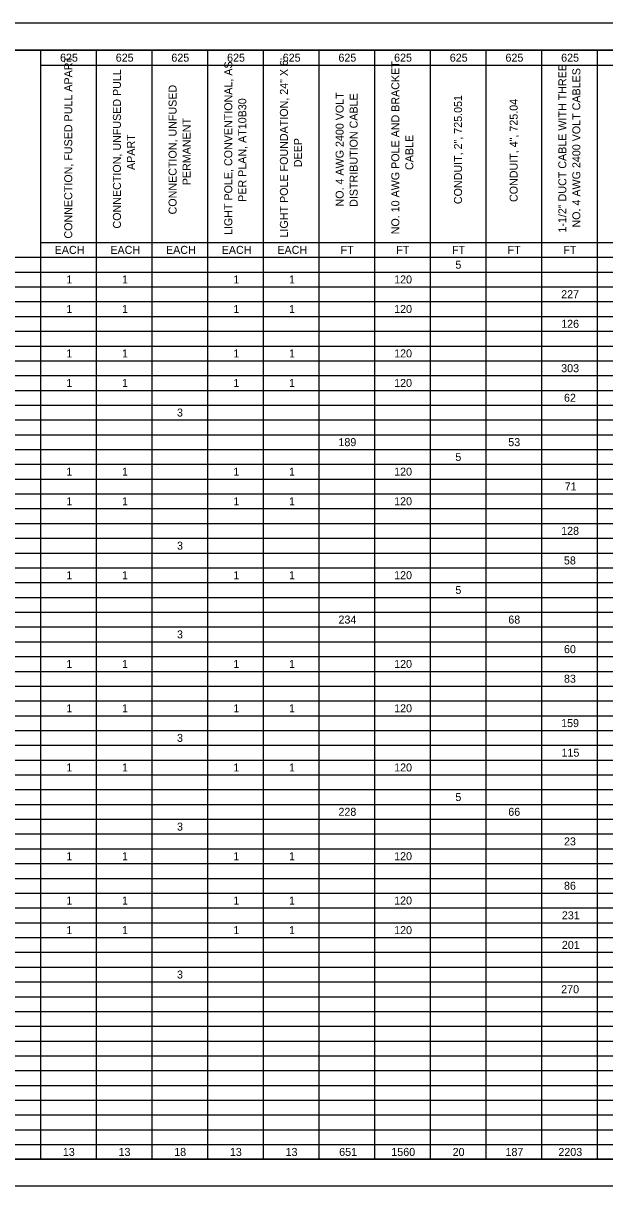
# Model space of a CAD drawing. Extents: x 0 to 34, y 0 to 22.
# Drawn here: x 11.66 to 22.66, y 0 to 22 of the extents above; entities that cross this region are included whole.
import ezdxf

# ---------------------------------------------------------------- set-up
doc = ezdxf.new("R2010")
doc.units = 0
for name, color, linetype in [('Default', 7, 'Continuous'), ('SH_Border', 7, 'Continuous'), ('SH_Cut_Line', 7, 'Continuous')]:
    doc.layers.add(name, color=color, linetype=linetype)

msp = doc.modelspace()

# ---------------------------------------------------------------- linework, layer by layer
at = {"layer": 'Default'}
for p, q in [((1.496, 21.489), (32, 21.489)), ((11.982, 21.489), (11.982, 0.78)), ((13.036, 21.489), (13.036, 0.5)), ((14.089, 21.489), (14.089, 0.5)), ((15.143, 21.489), (15.143, 0.5)), ((16.196, 21.489), (16.196, 0.5)), ((17.25, 21.489), (17.25, 0.5)), ((18.304, 21.489), (18.304, 0.5)), ((19.357, 21.489), (19.357, 0.5)), ((20.411, 21.489), (20.411, 0.5)), ((21.464, 21.489), (21.464, 0.5)), ((22.518, 21.489), (22.518, 0.5)), ((11.982, 21.209), (32, 21.209)), ((11.982, 17.851), (32, 17.851)), ((1.496, 17.571), (32, 17.571)), ((1.496, 17.291), (32, 17.291)), ((1.496, 17.011), (32, 17.011)), ((1.496, 16.732), (32, 16.732)), ((1.496, 16.452), (32, 16.452)), ((1.496, 16.172), (32, 16.172)), ((1.496, 15.892), (32, 15.892)), ((1.496, 15.612), (32, 15.612)), ((1.496, 15.332), (32, 15.332)), ((1.496, 15.052), (32, 15.052)), ((1.496, 14.773), (32, 14.773)), ((1.496, 14.493), (32, 14.493)), ((1.496, 14.213), (32, 14.213)), ((1.496, 13.933), (32, 13.933)), ((1.496, 13.653), (32, 13.653)), ((1.496, 13.373), (32, 13.373)), ((1.496, 13.093), (32, 13.093)), ((1.496, 12.814), (32, 12.814)), ((1.496, 12.534), (32, 12.534)), ((1.496, 12.254), (32, 12.254)), ((1.496, 11.974), (32, 11.974)), ((1.496, 11.694), (32, 11.694)), ((1.496, 11.414), (32, 11.414)), ((1.496, 11.134), (32, 11.134)), ((1.496, 10.855), (32, 10.855)), ((1.496, 10.575), (32, 10.575)), ((1.496, 10.295), (32, 10.295)), ((1.496, 10.015), (32, 10.015)), ((1.496, 9.735), (32, 9.735)), ((1.496, 9.455), (32, 9.455)), ((1.496, 9.175), (32, 9.175)), ((1.496, 8.896), (32, 8.896)), ((1.496, 8.616), (32, 8.616)), ((1.496, 8.336), (32, 8.336)), ((1.496, 8.056), (32, 8.056)), ((1.496, 7.776), (32, 7.776)), ((1.496, 7.496), (32, 7.496)), ((1.496, 7.217), (32, 7.217)), ((1.496, 6.937), (32, 6.937)), ((1.496, 6.657), (32, 6.657)), ((1.496, 6.377), (32, 6.377)), ((1.496, 6.097), (32, 6.097)), ((1.496, 5.817), (32, 5.817)), ((1.496, 5.537), (32, 5.537)), ((1.496, 5.258), (32, 5.258)), ((1.496, 4.978), (32, 4.978)), ((1.496, 4.698), (32, 4.698)), ((1.496, 4.418), (32, 4.418)), ((1.496, 4.138), (32, 4.138)), ((1.496, 3.858), (32, 3.858)), ((1.496, 3.578), (32, 3.578)), ((1.496, 3.299), (32, 3.299)), ((1.496, 3.019), (32, 3.019)), ((1.496, 2.739), (32, 2.739)), ((1.496, 2.459), (32, 2.459)), ((1.496, 2.179), (32, 2.179)), ((1.496, 1.899), (32, 1.899)), ((1.496, 1.619), (32, 1.619)), ((1.496, 1.34), (32, 1.34)), ((1.496, 1.06), (32, 1.06)), ((1.496, 0.78), (32, 0.78)), ((11.982, 0.78), (11.982, 0.5)), ((1.496, 0.5), (32, 0.5))]:
    msp.add_line(p, q, dxfattribs=at)
at = {"layer": 'SH_Border'}
msp.add_lwpolyline([(1.5, 21.5), (33.5, 21.5), (33.5, 0.5), (1.5, 0.5)], close=True, dxfattribs=at)
at = {"layer": 'SH_Cut_Line'}
msp.add_lwpolyline([(0, 0), (34, 0), (34, 22), (0, 22)], close=True, dxfattribs=at)

# ---------------------------------------------------------------- texts
at = {"layer": 'Default'}
for s, height, p in [('625', 0.1515, (12.354, 21.273)), ('625', 0.1515, (13.408, 21.273)), ('625', 0.1515, (14.461, 21.273)), ('625', 0.1515, (15.515, 21.273)), ('625', 0.1515, (16.568, 21.273)), ('625', 0.1515, (17.622, 21.273)), ('625', 0.1515, (18.675, 21.273)), ('625', 0.1515, (19.729, 21.273)), ('625', 0.1515, (20.783, 21.273)), ('625', 0.1515, (21.836, 21.273)), ('EACH', 0.1515, (12.252, 17.635)), ('EACH', 0.1515, (13.306, 17.635)), ('EACH', 0.1515, (14.359, 17.635)), ('EACH', 0.1515, (15.413, 17.635)), ('EACH', 0.1515, (16.466, 17.635)), ('FT', 0.1515, (17.662, 17.635)), ('FT', 0.1515, (18.716, 17.635)), ('FT', 0.1515, (19.77, 17.635)), ('FT', 0.1515, (20.823, 17.635)), ('FT', 0.1515, (21.877, 17.635)), ('5', 0.151, (19.835, 17.355)), ('1', 0.151, (12.474, 17.076)), ('1', 0.151, (13.527, 17.076)), ('1', 0.151, (15.634, 17.076)), ('1', 0.151, (16.688, 17.076)), ('120', 0.1515, (18.676, 17.076)), ('227', 0.1515, (21.837, 16.796)), ('1', 0.151, (12.474, 16.516)), ('1', 0.151, (13.527, 16.516)), ('1', 0.151, (15.634, 16.516)), ('1', 0.151, (16.688, 16.516)), ('120', 0.1515, (18.676, 16.516)), ('126', 0.1515, (21.837, 16.236)), ('1', 0.151, (12.474, 15.676)), ('1', 0.151, (13.527, 15.676)), ('1', 0.151, (15.634, 15.676)), ('1', 0.151, (16.688, 15.676)), ('120', 0.1515, (18.676, 15.676)), ('303', 0.1515, (21.837, 15.396)), ('1', 0.151, (12.474, 15.117)), ('1', 0.151, (13.527, 15.117)), ('1', 0.151, (15.634, 15.117)), ('1', 0.151, (16.688, 15.117)), ('120', 0.1515, (18.676, 15.117)), ('62', 0.1515, (21.89, 14.837)), ('3', 0.151, (14.567, 14.557)), ('189', 0.1515, (17.622, 13.997)), ('53', 0.1515, (20.836, 13.997)), ('5', 0.151, (19.835, 13.717)), ('1', 0.151, (12.474, 13.438)), ('1', 0.151, (13.527, 13.438)), ('1', 0.151, (15.634, 13.438)), ('1', 0.151, (16.688, 13.438)), ('120', 0.1515, (18.676, 13.438)), ('71', 0.1515, (21.903, 13.158)), ('1', 0.151, (12.474, 12.878)), ('1', 0.151, (13.527, 12.878)), ('1', 0.151, (15.634, 12.878)), ('1', 0.151, (16.688, 12.878)), ('120', 0.1515, (18.676, 12.878)), ('128', 0.1515, (21.836, 12.318)), ('3', 0.151, (14.567, 12.038)), ('58', 0.1515, (21.889, 11.758)), ('1', 0.151, (12.474, 11.479)), ('1', 0.151, (13.527, 11.479)), ('1', 0.151, (15.634, 11.479)), ('1', 0.151, (16.688, 11.479)), ('120', 0.1515, (18.676, 11.479)), ('5', 0.151, (19.835, 11.199)), ('234', 0.1515, (17.623, 10.639)), ('68', 0.1515, (20.836, 10.639)), ('3', 0.151, (14.567, 10.359)), ('60', 0.1515, (21.89, 10.079)), ('1', 0.151, (12.474, 9.799)), ('1', 0.151, (13.527, 9.799)), ('1', 0.151, (15.634, 9.799)), ('1', 0.151, (16.688, 9.799)), ('120', 0.1515, (18.676, 9.799)), ('83', 0.1515, (21.89, 9.52)), ('1', 0.151, (12.474, 8.96)), ('1', 0.151, (13.527, 8.96)), ('1', 0.151, (15.634, 8.96)), ('1', 0.151, (16.688, 8.96)), ('120', 0.1515, (18.676, 8.96)), ('159', 0.1515, (21.836, 8.68)), ('3', 0.151, (14.567, 8.4)), ('115', 0.1515, (21.843, 8.12)), ('1', 0.151, (12.474, 7.84)), ('1', 0.151, (13.527, 7.84)), ('1', 0.151, (15.634, 7.84)), ('1', 0.151, (16.688, 7.84)), ('120', 0.1515, (18.676, 7.84)), ('5', 0.151, (19.835, 7.281)), ('228', 0.1515, (17.622, 7.001)), ('66', 0.1515, (20.836, 7.001)), ('3', 0.151, (14.567, 6.721)), ('23', 0.1515, (21.89, 6.441)), ('1', 0.151, (12.474, 6.161)), ('1', 0.151, (13.527, 6.161)), ('1', 0.151, (15.634, 6.161)), ('1', 0.151, (16.688, 6.161)), ('120', 0.1515, (18.676, 6.161)), ('86', 0.1515, (21.89, 5.602)), ('1', 0.151, (12.474, 5.322)), ('1', 0.151, (13.527, 5.322)), ('1', 0.151, (15.634, 5.322)), ('1', 0.151, (16.688, 5.322)), ('120', 0.1515, (18.676, 5.322)), ('231', 0.1515, (21.85, 5.042)), ('1', 0.151, (12.474, 4.762)), ('1', 0.151, (13.527, 4.762)), ('1', 0.151, (15.634, 4.762)), ('1', 0.151, (16.688, 4.762)), ('120', 0.1515, (18.676, 4.762)), ('201', 0.1515, (21.85, 4.482)), ('3', 0.151, (14.567, 3.922)), ('270', 0.1515, (21.837, 3.643)), ('13', 0.1515, (12.407, 0.564)), ('13', 0.1515, (13.461, 0.564)), ('18', 0.1515, (14.514, 0.564)), ('13', 0.1515, (15.568, 0.564)), ('13', 0.1515, (16.622, 0.564)), ('651', 0.1515, (17.636, 0.564)), ('1560', 0.1515, (18.623, 0.564)), ('20', 0.1515, (19.783, 0.564)), ('187', 0.1515, (20.783, 0.564)), ('2203', 0.1515, (21.784, 0.564))]:
    msp.add_text(s, height=height, dxfattribs=at).set_placement(p)
for s, height, p in [('CONNECTION, FUSED PULL APART', 0.15145, (12.585, 17.925)), ('CONNECTION, UNFUSED PULL ', 0.15145, (13.506, 18.115)), ('LIGHT POLE, CONVENTIONAL, AS ', 0.15145, (15.613, 17.992)), ('LIGHT POLE FOUNDATION, 24" X 6\' ', 0.15145, (16.666, 17.946)), ('NO. 10 AWG POLE AND BRACKET ', 0.15145, (18.774, 18.006)), ('1-1/2" DUCT CABLE WITH THREE ', 0.15145, (21.934, 18.039)), ('NO. 4 AWG 2400 VOLT CABLES', 0.15145, (22.199, 18.134)), ('CONNECTION, UNFUSED ', 0.15145, (14.559, 18.382)), ('NO. 4 AWG 2400 VOLT ', 0.15145, (17.72, 18.532)), ('PER PLAN, AT10B30', 0.15145, (15.878, 18.621)), ('DISTRIBUTION CABLE', 0.15145, (17.985, 18.525)), ('CONDUIT, 2", 725.051', 0.15145, (19.96, 18.577)), ('CONDUIT, 4", 725.04', 0.15145, (21.013, 18.617)), ('PERMANENT', 0.1515, (14.824, 18.934)), ('APART', 0.1515, (13.771, 19.223)), ('DEEP', 0.1515, (16.931, 19.275)), ('CABLE', 0.1515, (19.039, 19.223))]:
    msp.add_text(s, height=height, rotation=90, dxfattribs=at).set_placement(p)

doc.saveas('drawing.dxf')
